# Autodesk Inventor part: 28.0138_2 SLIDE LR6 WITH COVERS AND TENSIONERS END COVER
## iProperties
Created: 2007-06
Part Number: 28.0138_2 SLIDE LR6 WITH COVERS AND TENSIONERS END COVER
Document SubType Name: Modeling
Designer: Andy Moles
Material: ABS Plastic
Mass: 13.348 g
Surface Area: 87.9545 cm^2
Volume: 12.5924 cm^3
Density: 1.06 g/cm^3
Author: Andy Moles
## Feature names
1. Base1
2. Extrusion1
